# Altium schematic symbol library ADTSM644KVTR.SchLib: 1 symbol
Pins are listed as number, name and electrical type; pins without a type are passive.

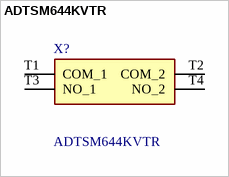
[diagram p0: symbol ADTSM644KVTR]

## ADTSM644KVTR
designator X?
Tactile Switches SW TACT SPST 0.05A 12VDC 6MM; Manufacturer_Name: Apem; Geometry.Height: 7.3mm
footprint ADTSM644KVTR
pins: T1 COM_1, T2 COM_2, T3 NO_1, T4 NO_2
